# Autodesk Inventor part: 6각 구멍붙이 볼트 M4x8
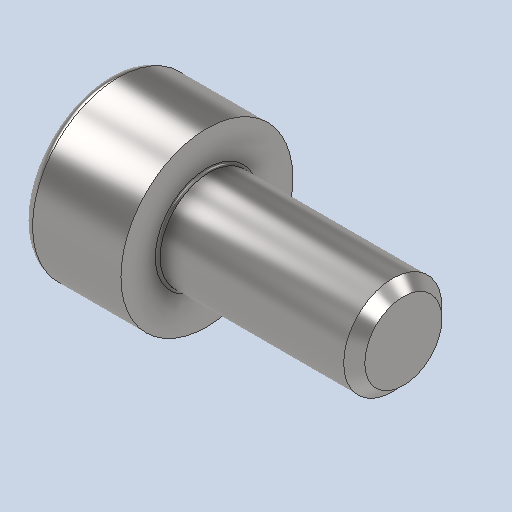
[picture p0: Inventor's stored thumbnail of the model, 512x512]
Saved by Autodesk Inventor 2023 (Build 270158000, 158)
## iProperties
Created: 2026-06
Part Number: 6각 구멍붙이 볼트 M4x8
Material: 강철, 연강
Description: 6각머리 태핑 나사
Document SubType Name: Modeling
Designer: 4강의실
Density: 7.85 g/cm^3
Appearance: 기본값
Author: jhkim
Sending System: Autodesk Inventor 2027
Preprocessor: ST-DEVELOPER v20.1
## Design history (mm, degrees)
feature "Solid1"
node "솔리드1"
